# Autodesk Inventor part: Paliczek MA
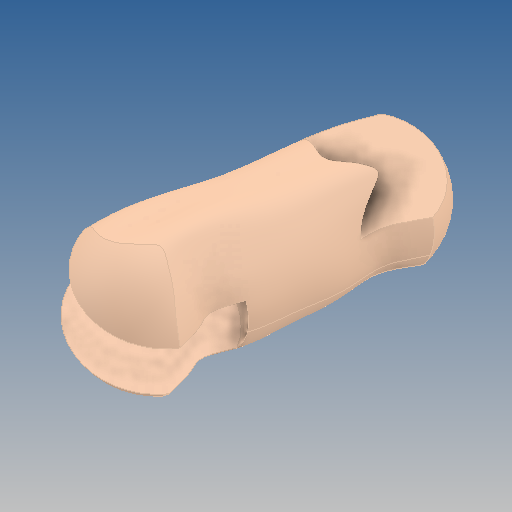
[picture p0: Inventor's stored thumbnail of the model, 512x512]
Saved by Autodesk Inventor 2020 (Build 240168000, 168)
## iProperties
Created: 2019-10
Part Number: Paliczek MA
Material: GFRP
Document SubType Name: Modeling
Designer: yello
Density: 1.75 g/cm^3
Appearance: Default
Author: yello
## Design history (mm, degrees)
feature "Paliczek MA"
body "Solid1"
